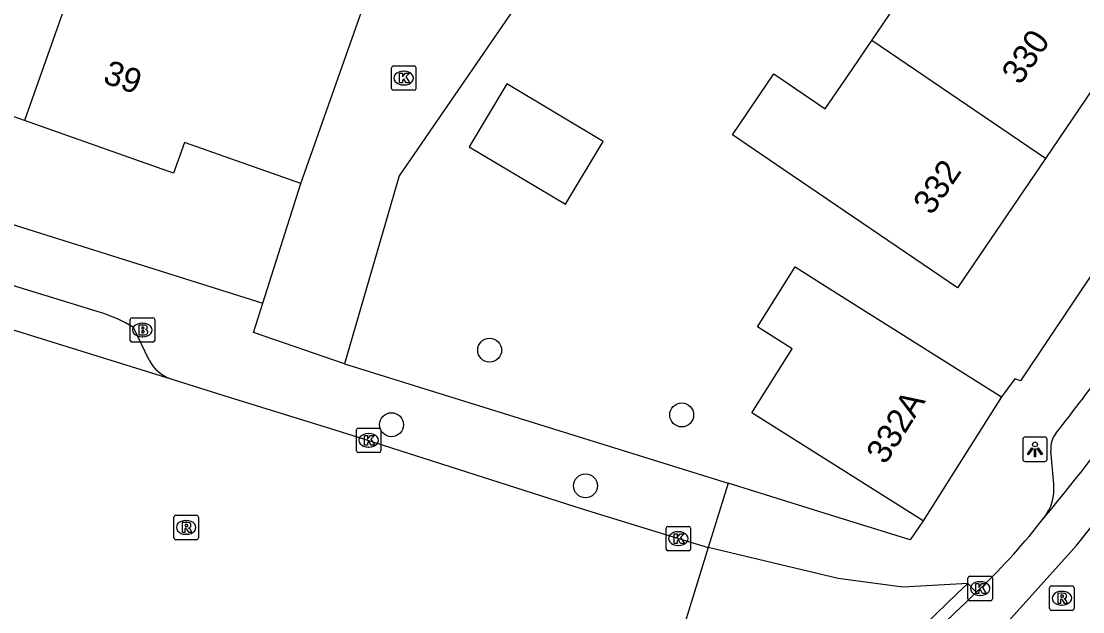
# Model space of a CAD drawing. Extents: x 160557 to 161245, y 385330 to 386505.
# Drawn here: x 160874.1 to 160917.52, y 385915.16 to 385939.3 of the extents above; entities that cross this region are included whole.
import ezdxf

# ---------------------------------------------------------------- set-up
doc = ezdxf.new("R2010")
doc.units = 0
for name, color, linetype in [('IMGEO_Boom', 7, 'Continuous'), ('IMGEO_Brandkraan', 7, 'Continuous'), ('IMGEO_Kolk', 7, 'Continuous'), ('IMGEO_Lichtpunt', 7, 'Continuous'), ('IMGEO_Pand', 7, 'Continuous'), ('IMGEO_Pand_nummerreeks', 7, 'Continuous'), ('IMGEO_Rijbaan_lokaal_gesloten', 7, 'Continuous'), ('IMGEO_Rijbaan_lokaal_open', 7, 'Continuous'), ('IMGEO_Rioolput', 7, 'Continuous'), ('IMGEO_Voetpad_open', 7, 'Continuous')]:
    doc.layers.add(name, color=color, linetype=linetype)

msp = doc.modelspace()

# ---------------------------------------------------------------- linework, layer by layer
at = {"layer": 'IMGEO_Boom'}
for centre in [(160893.26, 385925.855), (160901.114, 385923.205), (160889.249, 385922.806), (160897.18, 385920.308)]:
    msp.add_circle(centre, 0.489, dxfattribs=at)
at = {"layer": 'IMGEO_Brandkraan'}
for p, q in [((160878.635, 385927.18), (160879.487, 385927.18)), ((160878.56, 385926.254), (160878.56, 385927.106)), ((160879.048, 385926.96), (160879.073, 385926.96)), ((160879.561, 385927.106), (160879.561, 385926.254)), ((160879.071, 385926.4), (160879.046, 385926.4)), ((160879.487, 385926.18), (160878.635, 385926.18))]:
    msp.add_line(p, q, dxfattribs=at)
for points in [[(160878.635, 385927.18), (160879.487, 385927.18)], [(160878.56, 385926.254), (160878.56, 385927.106)], [(160878.908, 385926.88), (160878.908, 385926.48), (160879.121, 385926.48)], [(160879.139, 385926.88), (160878.908, 385926.88)], [(160879.087, 385926.799), (160879.033, 385926.799), (160879.033, 385926.723)], [(160879.033, 385926.723), (160879.086, 385926.723)], [(160879.561, 385927.106), (160879.561, 385926.254)], [(160879.095, 385926.647), (160879.033, 385926.647), (160879.033, 385926.566)], [(160879.033, 385926.566), (160879.095, 385926.566)], [(160879.487, 385926.18), (160878.635, 385926.18)]]:
    msp.add_lwpolyline(points, dxfattribs=at)
for centre, radius, start, end in [((160878.637, 385927.104), 0.0765, 91.552, 178.448), ((160878.637, 385927.104), 0.0765, 91.552, 178.448), ((160879.485, 385927.104), 0.0765, 1.552, 88.448), ((160879.485, 385927.104), 0.0765, 1.552, 88.448), ((160879.088, 385926.761), 0.0379, 267.8285, 90.9355), ((160879.143, 385926.735), 0.145, 59.4692, 91.5367), ((160879.168, 385926.782), 0.0922, 285.5137, 58.1501), ((160879.096, 385926.606), 0.0404, 269.8759, 90.5077), ((160879.127, 385926.731), 0.251, 268.6676, 293.5347), ((160879.173, 385926.59), 0.105, 301.3115, 78.989), ((160878.637, 385926.256), 0.0765, 181.552, 268.448), ((160878.637, 385926.256), 0.0765, 181.552, 268.448), ((160879.485, 385926.256), 0.0765, 271.552, 358.448), ((160879.485, 385926.256), 0.0765, 271.552, 358.448)]:
    msp.add_arc(centre, radius, start, end, dxfattribs=at)
for centre, major_axis, ratio, start_param, end_param in [((160879.047, 385926.68), (-0.387, 0.002), 0.722429, 4.712389, 7.853982), ((160879.072, 385926.68), (-0.39, 0.002), 0.717154, 1.570796, 4.712389)]:
    msp.add_ellipse(centre, major_axis=major_axis, ratio=ratio, start_param=start_param, end_param=end_param, dxfattribs=at)
at = {"layer": 'IMGEO_Kolk'}
for p, q in [((160889.247, 385936.552), (160889.247, 385937.404)), ((160889.322, 385937.478), (160890.174, 385937.478)), ((160889.735, 385937.258), (160889.76, 385937.258)), ((160890.248, 385937.404), (160890.248, 385936.552)), ((160889.758, 385936.698), (160889.733, 385936.698)), ((160890.174, 385936.478), (160889.322, 385936.478)), ((160887.815, 385921.742), (160887.815, 385922.594)), ((160887.89, 385922.668), (160888.742, 385922.668)), ((160888.303, 385922.448), (160888.328, 385922.448)), ((160888.816, 385922.594), (160888.816, 385921.742)), ((160888.742, 385921.668), (160887.89, 385921.668)), ((160888.326, 385921.888), (160888.301, 385921.888)), ((160900.479, 385917.724), (160900.479, 385918.576)), ((160900.554, 385918.65), (160901.406, 385918.65)), ((160901.48, 385918.576), (160901.48, 385917.724)), ((160900.967, 385918.43), (160900.992, 385918.43)), ((160901.406, 385917.65), (160900.554, 385917.65)), ((160900.99, 385917.87), (160900.965, 385917.87)), ((160912.82, 385915.682), (160912.82, 385916.534)), ((160912.895, 385916.608), (160913.747, 385916.608)), ((160913.308, 385916.388), (160913.333, 385916.388)), ((160913.821, 385916.534), (160913.821, 385915.682)), ((160913.747, 385915.608), (160912.895, 385915.608)), ((160913.331, 385915.828), (160913.306, 385915.828))]:
    msp.add_line(p, q, dxfattribs=at)
for points in [[(160889.247, 385936.552), (160889.247, 385937.404)], [(160889.322, 385937.478), (160890.174, 385937.478)], [(160889.568, 385937.178), (160889.691, 385937.178), (160889.691, 385937.027), (160889.821, 385937.178), (160889.985, 385937.178), (160889.839, 385937.027), (160889.992, 385936.778), (160889.84, 385936.778), (160889.755, 385936.942), (160889.691, 385936.875), (160889.691, 385936.778), (160889.568, 385936.778), (160889.568, 385937.178)], [(160890.248, 385937.404), (160890.248, 385936.552)], [(160890.174, 385936.478), (160889.322, 385936.478)], [(160887.815, 385921.742), (160887.815, 385922.594)], [(160887.89, 385922.668), (160888.742, 385922.668)], [(160888.136, 385922.368), (160888.259, 385922.368), (160888.259, 385922.217), (160888.389, 385922.368), (160888.553, 385922.368), (160888.407, 385922.217), (160888.56, 385921.968), (160888.408, 385921.968), (160888.323, 385922.132), (160888.259, 385922.065), (160888.259, 385921.968), (160888.136, 385921.968), (160888.136, 385922.368)], [(160888.816, 385922.594), (160888.816, 385921.742)], [(160888.742, 385921.668), (160887.89, 385921.668)], [(160900.479, 385917.724), (160900.479, 385918.576)], [(160900.554, 385918.65), (160901.406, 385918.65)], [(160901.48, 385918.576), (160901.48, 385917.724)], [(160900.8, 385918.35), (160900.923, 385918.35), (160900.923, 385918.199), (160901.053, 385918.35), (160901.217, 385918.35), (160901.071, 385918.199), (160901.224, 385917.95), (160901.072, 385917.95), (160900.987, 385918.114), (160900.923, 385918.047), (160900.923, 385917.95), (160900.8, 385917.95), (160900.8, 385918.35)], [(160901.406, 385917.65), (160900.554, 385917.65)], [(160912.82, 385915.682), (160912.82, 385916.534)], [(160912.895, 385916.608), (160913.747, 385916.608)], [(160913.141, 385916.308), (160913.264, 385916.308), (160913.264, 385916.157), (160913.394, 385916.308), (160913.558, 385916.308), (160913.412, 385916.157), (160913.565, 385915.908), (160913.413, 385915.908), (160913.328, 385916.072), (160913.264, 385916.005), (160913.264, 385915.908), (160913.141, 385915.908), (160913.141, 385916.308)], [(160913.821, 385916.534), (160913.821, 385915.682)], [(160913.747, 385915.608), (160912.895, 385915.608)]]:
    msp.add_lwpolyline(points, dxfattribs=at)
for centre, start, end in [((160889.324, 385937.402), 91.552, 178.448), ((160889.324, 385937.402), 91.552, 178.448), ((160890.172, 385937.402), 1.552, 88.448), ((160890.172, 385937.402), 1.552, 88.448), ((160889.324, 385936.554), 181.552, 268.448), ((160889.324, 385936.554), 181.552, 268.448), ((160890.172, 385936.554), 271.552, 358.448), ((160890.172, 385936.554), 271.552, 358.448), ((160887.892, 385922.592), 91.552, 178.448), ((160887.892, 385922.592), 91.552, 178.448), ((160888.74, 385922.592), 1.552, 88.448), ((160888.74, 385922.592), 1.552, 88.448), ((160887.892, 385921.744), 181.552, 268.448), ((160887.892, 385921.744), 181.552, 268.448), ((160888.74, 385921.744), 271.552, 358.448), ((160888.74, 385921.744), 271.552, 358.448), ((160900.556, 385918.574), 91.552, 178.448), ((160900.556, 385918.574), 91.552, 178.448), ((160901.404, 385918.574), 1.552, 88.448), ((160901.404, 385918.574), 1.552, 88.448), ((160900.556, 385917.726), 181.552, 268.448), ((160900.556, 385917.726), 181.552, 268.448), ((160901.404, 385917.726), 271.552, 358.448), ((160901.404, 385917.726), 271.552, 358.448), ((160912.897, 385916.532), 91.552, 178.448), ((160912.897, 385916.532), 91.552, 178.448), ((160913.745, 385916.532), 1.552, 88.448), ((160913.745, 385916.532), 1.552, 88.448), ((160912.897, 385915.684), 181.552, 268.448), ((160912.897, 385915.684), 181.552, 268.448), ((160913.745, 385915.684), 271.552, 358.448), ((160913.745, 385915.684), 271.552, 358.448)]:
    msp.add_arc(centre, 0.0765, start, end, dxfattribs=at)
for centre, major_axis, ratio, start_param, end_param in [((160889.734, 385936.978), (-0.387, 0.002), 0.722429, 4.712389, 7.853982), ((160889.759, 385936.978), (-0.39, 0.002), 0.717154, 1.570796, 4.712389), ((160888.302, 385922.168), (-0.387, 0.002), 0.722429, 4.712389, 7.853982), ((160888.327, 385922.168), (-0.39, 0.002), 0.717154, 1.570796, 4.712389), ((160900.966, 385918.15), (-0.387, 0.002), 0.722429, 4.712389, 7.853982), ((160900.991, 385918.15), (-0.39, 0.002), 0.717154, 1.570796, 4.712389), ((160913.307, 385916.108), (-0.387, 0.002), 0.722429, 4.712389, 7.853982), ((160913.332, 385916.108), (-0.39, 0.002), 0.717154, 1.570796, 4.712389)]:
    msp.add_ellipse(centre, major_axis=major_axis, ratio=ratio, start_param=start_param, end_param=end_param, dxfattribs=at)
at = {"layer": 'IMGEO_Lichtpunt'}
for p, q in [((160915.063, 385922.203), (160915.063, 385921.396)), ((160915.063, 385922.203), (160915.063, 385921.396)), ((160915.965, 385922.298), (160915.157, 385922.298)), ((160915.965, 385922.298), (160915.157, 385922.298)), ((160916.059, 385921.396), (160916.059, 385922.203)), ((160916.059, 385921.396), (160916.059, 385922.203)), ((160915.157, 385921.302), (160915.965, 385921.302)), ((160915.157, 385921.302), (160915.965, 385921.302))]:
    msp.add_line(p, q, dxfattribs=at)
for points in [[(160915.437, 385921.867), (160915.476, 385921.839), (160915.288, 385921.577), (160915.25, 385921.604), (160915.437, 385921.867)], [(160915.539, 385921.819), (160915.586, 385921.819), (160915.586, 385921.497), (160915.539, 385921.497), (160915.539, 385921.819)], [(160915.649, 385921.839), (160915.687, 385921.866), (160915.874, 385921.604), (160915.835, 385921.576), (160915.649, 385921.839)]]:
    msp.add_lwpolyline(points, dxfattribs=at)
msp.add_circle((160915.562, 385922.001), 0.0994, dxfattribs=at)
for centre, start, end in [((160915.157, 385922.203), 90, 180), ((160915.157, 385922.203), 90, 180), ((160915.965, 385922.203), 0, 90), ((160915.965, 385922.203), 0, 90), ((160915.157, 385921.396), 180, 270), ((160915.157, 385921.396), 180, 270), ((160915.965, 385921.396), 270, 0), ((160915.965, 385921.396), 270, 360)]:
    msp.add_arc(centre, 0.0946, start, end, dxfattribs=at)
at = {"layer": 'IMGEO_Pand'}
for points in [[(160908.889, 385938.514), (160912.454, 385943.758)], [(160877.122, 385943.426), (160874.235, 385935.243)], [(160885.54, 385932.667), (160888.841, 385942.021)], [(160919.552, 385938.935), (160915.988, 385933.69)], [(160915.988, 385933.69), (160912.395, 385928.404), (160905.297, 385933.228), (160903.192, 385934.658), (160904.884, 385937.147), (160906.988, 385935.716), (160908.108, 385937.364), (160908.889, 385938.514)], [(160915.988, 385933.69), (160908.889, 385938.514)], [(160874.235, 385935.243), (160868.3, 385937.337)], [(160892.428, 385934.17), (160896.366, 385931.823), (160897.896, 385934.391), (160893.958, 385936.738), (160892.428, 385934.17)], [(160885.54, 385932.667), (160880.779, 385934.348), (160880.335, 385933.09), (160874.235, 385935.243)], [(160910.994, 385918.872), (160903.977, 385923.289), (160905.629, 385925.913), (160904.214, 385926.804), (160905.758, 385929.257), (160907.173, 385928.367), (160914.19, 385923.951)], [(160914.19, 385923.951), (160910.994, 385918.872)]]:
    msp.add_lwpolyline(points, dxfattribs=at)
at = {"layer": 'IMGEO_Rijbaan_lokaal_gesloten'}
for points in [[(160872.467, 385851.189), (160885.466, 385872.996), (160893.23, 385886.069), (160896.724, 385891.912), (160899.657, 385896.647), (160902.182, 385900.473), (160903.908, 385902.895), (160907.161, 385907.035), (160910.647, 385910.965), (160914.591, 385914.901), (160917.267, 385917.867), (160920.016, 385921.325), (160923.521, 385926.184), (160926.798, 385931.115)], [(160860.248, 385930.666), (160866.444, 385928.966), (160880.216, 385924.684)], [(160880.216, 385924.684), (160882.61, 385923.939), (160886.758, 385922.649), (160887.881, 385922.3), (160897.048, 385919.373), (160900.98, 385918.15), (160902.196, 385917.781)], [(160902.196, 385917.781), (160900.799, 385913.232)], [(160913.162, 385915.955), (160913.322, 385916.107)]]:
    msp.add_lwpolyline(points, dxfattribs=at)
for centre, radius, start, end in [((160831.635, 385988.777), 109.429, 320.383, 327.29334), ((160894.859, 385935.386), 26.694, 313.7612, 322.1287), ((160974.708, 385850.625), 89.755, 133.29177, 145.49978)]:
    msp.add_arc(centre, radius, start, end, dxfattribs=at)
at = {"layer": 'IMGEO_Rijbaan_lokaal_open'}
for points in [[(160903.683, 385953.624), (160901.859, 385950.881), (160889.565, 385932.976), (160887.33, 385925.297)], [(160883.981, 385927.769), (160885.54, 385932.667)], [(160887.33, 385925.297), (160883.599, 385926.57), (160883.981, 385927.769)]]:
    msp.add_lwpolyline(points, dxfattribs=at)
at = {"layer": 'IMGEO_Rioolput'}
for p, q in [((160880.348, 385918.18), (160880.348, 385919.032)), ((160880.423, 385919.106), (160881.275, 385919.106)), ((160881.349, 385919.032), (160881.349, 385918.18)), ((160880.836, 385918.886), (160880.861, 385918.886)), ((160881.275, 385918.106), (160880.423, 385918.106)), ((160880.859, 385918.326), (160880.834, 385918.326)), ((160916.161, 385915.287), (160916.161, 385916.139)), ((160916.236, 385916.213), (160917.088, 385916.213)), ((160916.649, 385915.993), (160916.674, 385915.993)), ((160917.162, 385916.139), (160917.162, 385915.287)), ((160916.672, 385915.433), (160916.647, 385915.433)), ((160917.088, 385915.213), (160916.236, 385915.213))]:
    msp.add_line(p, q, dxfattribs=at)
for points in [[(160880.348, 385918.18), (160880.348, 385919.032)], [(160880.423, 385919.106), (160881.275, 385919.106)], [(160881.349, 385919.032), (160881.349, 385918.18)], [(160880.937, 385918.804), (160880.685, 385918.806), (160880.685, 385918.406)], [(160880.685, 385918.406), (160880.809, 385918.406), (160880.809, 385918.568), (160880.82, 385918.568)], [(160880.863, 385918.725), (160880.809, 385918.725), (160880.809, 385918.644)], [(160880.809, 385918.644), (160880.861, 385918.644)], [(160880.867, 385918.539), (160880.938, 385918.406), (160881.078, 385918.406), (160881.013, 385918.532)], [(160881.275, 385918.106), (160880.423, 385918.106)], [(160916.161, 385915.287), (160916.161, 385916.139)], [(160916.236, 385916.213), (160917.088, 385916.213)], [(160916.75, 385915.911), (160916.498, 385915.913), (160916.498, 385915.513)], [(160917.162, 385916.139), (160917.162, 385915.287)], [(160916.498, 385915.513), (160916.622, 385915.513), (160916.622, 385915.675), (160916.633, 385915.675)], [(160916.676, 385915.832), (160916.622, 385915.832), (160916.622, 385915.751)], [(160916.622, 385915.751), (160916.674, 385915.751)], [(160916.68, 385915.646), (160916.751, 385915.513), (160916.891, 385915.513), (160916.826, 385915.639)], [(160917.088, 385915.213), (160916.236, 385915.213)]]:
    msp.add_lwpolyline(points, dxfattribs=at)
for centre, radius, start, end in [((160880.425, 385919.03), 0.0765, 91.552, 178.448), ((160880.425, 385919.03), 0.0765, 91.552, 178.448), ((160881.273, 385919.03), 0.0765, 1.552, 88.448), ((160881.273, 385919.03), 0.0765, 1.552, 88.448), ((160880.819, 385918.515), 0.0533, 26.0293, 88.6989), ((160880.845, 385918.833), 0.19, 274.7715, 282.9687), ((160880.869, 385918.629), 0.0964, 77.0061, 93.1865), ((160880.883, 385918.686), 0.0378, 276.6634, 79.6772), ((160880.936, 385918.694), 0.109, 350.3612, 89.416), ((160880.934, 385918.694), 0.112, 277.5842, 350.9817), ((160880.918, 385918.479), 0.108, 29.5134, 73.7905), ((160880.425, 385918.182), 0.0765, 181.552, 268.448), ((160880.425, 385918.182), 0.0765, 181.552, 268.448), ((160881.273, 385918.182), 0.0765, 271.552, 358.448), ((160881.273, 385918.182), 0.0765, 271.552, 358.448), ((160916.238, 385916.137), 0.0765, 91.552, 178.448), ((160916.238, 385916.137), 0.0765, 91.552, 178.448), ((160916.749, 385915.801), 0.109, 350.3612, 89.416), ((160917.086, 385916.137), 0.0765, 1.552, 88.448), ((160917.086, 385916.137), 0.0765, 1.552, 88.448), ((160916.632, 385915.622), 0.0533, 26.0293, 88.6989), ((160916.658, 385915.94), 0.19, 274.7715, 282.9687), ((160916.682, 385915.736), 0.0964, 77.0061, 93.1865), ((160916.696, 385915.793), 0.0378, 276.6634, 79.6772), ((160916.747, 385915.801), 0.112, 277.5842, 350.9817), ((160916.731, 385915.586), 0.108, 29.5134, 73.7905), ((160916.238, 385915.289), 0.0765, 181.552, 268.448), ((160916.238, 385915.289), 0.0765, 181.552, 268.448), ((160917.086, 385915.289), 0.0765, 271.552, 358.448), ((160917.086, 385915.289), 0.0765, 271.552, 358.448)]:
    msp.add_arc(centre, radius, start, end, dxfattribs=at)
for centre, major_axis, ratio, start_param, end_param in [((160880.835, 385918.606), (-0.387, 0.002), 0.722429, 4.712389, 7.853982), ((160880.86, 385918.606), (-0.39, 0.002), 0.717154, 1.570796, 4.712389), ((160916.648, 385915.713), (-0.387, 0.002), 0.722429, 4.712389, 7.853982), ((160916.673, 385915.713), (-0.39, 0.002), 0.717154, 1.570796, 4.712389)]:
    msp.add_ellipse(centre, major_axis=major_axis, ratio=ratio, start_param=start_param, end_param=end_param, dxfattribs=at)
at = {"layer": 'IMGEO_Voetpad_open'}
for points in [[(160931.004, 385948.553), (160926.379, 385941.646), (160914.964, 385924.599), (160914.734, 385924.682), (160914.19, 385923.951)], [(160861.372, 385934.889), (160883.981, 385927.769)], [(160877.339, 385927.4), (160857.671, 385933.434)], [(160879.342, 385925.44), (160878.699, 385926.781)], [(160887.33, 385925.297), (160903.014, 385920.416)], [(160916.33, 385920.377), (160916.215, 385921.741)], [(160903.014, 385920.416), (160902.196, 385917.781)], [(160910.994, 385918.872), (160910.463, 385918.099), (160907.373, 385919.06), (160903.014, 385920.416)], [(160912.819, 385916.319), (160910.163, 385916.158), (160907.507, 385916.515), (160902.196, 385917.781)], [(160912.819, 385916.319), (160913.162, 385915.955)]]:
    msp.add_lwpolyline(points, dxfattribs=at)
for centre, radius, start, end in [((160831.642, 385989.036), 107.798, 321.86548, 325.58903), ((160875.554, 385921.675), 5.996, 58.3701, 72.6849), ((160880.737, 385926.169), 1.574, 207.6064, 250.6747), ((160917.192, 385921.847), 0.983, 140.6535, 186.1933), ((160914.421, 385920.183), 1.919, 321.9054, 5.7978), ((160974.773, 385850.568), 90.341, 133.29673, 145.49032)]:
    msp.add_arc(centre, radius, start, end, dxfattribs=at)

# ---------------------------------------------------------------- texts
at = {"layer": 'IMGEO_Pand_nummerreeks'}
for s, rotation, p in [('330', 55.7994, (160914.957, 385936.657)), ('39', 340.5619, (160877.399, 385936.799)), ('332', 55.8004, (160911.34, 385931.335)), ('332A', 57.8172, (160909.444, 385921.139))]:
    msp.add_text(s, height=1, rotation=rotation, dxfattribs=at).set_placement(p)

doc.saveas('drawing.dxf')
